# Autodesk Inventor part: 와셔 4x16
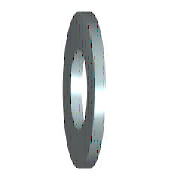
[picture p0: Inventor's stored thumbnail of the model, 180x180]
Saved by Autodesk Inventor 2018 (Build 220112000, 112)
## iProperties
IsCustomPart: 1
Created: 2012-02
Part Number: 와셔 4x16
Material: 강철, 연강
Description: 미터법 평면 와셔
Document SubType Name: Modeling
Standard: ANSI B18.22M
Designer: mduedu
Standard Revision: 1999
Standards Organization: ANSI
Language: ko-KR
Size Designation: 4 W
Categories: <MemberInstance><Categories><Category DisplayName="조임쇠" InternalName="e4da775c-781d-43d5-af7c-5136215cf5a6" Mnemonic="FSTN"><Category DisplayName="와셔" InternalN
Density: 1 g/cm^3
Appearance: 파란색 - 벽 페인트 - 광택
Author: mduedu
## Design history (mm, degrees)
sketch "스케치"
  geometry: C1 r 8 at (0, 0); C2 r 2.35 at (0, 0); 1 further point
  constraints: 2 centre point, 2 coincident
  dimensions: "d0" = 4.7 diameter of C2 (= SD1); "d1" = 16 diameter of C1 (= SD2)
extrude "본체" new body sketch "스케치" distance "d2" = 2.3 (= SD); taper "d3" = 0 deg
workaxis "Work Axis1"
workplane "Work Plane1"
body "Solid1"
other parameters: "SD1" = 4.7 [user parameter; used in 1 equation term], "SD2" = 16 [user parameter; used in 1 equation term], "SD" = 2.3 [user parameter; used in 1 equation term], "d4" = 0, "d5" = 0, "d6" = 0, "d7" = 0, "NND" = 4 [user parameter]
